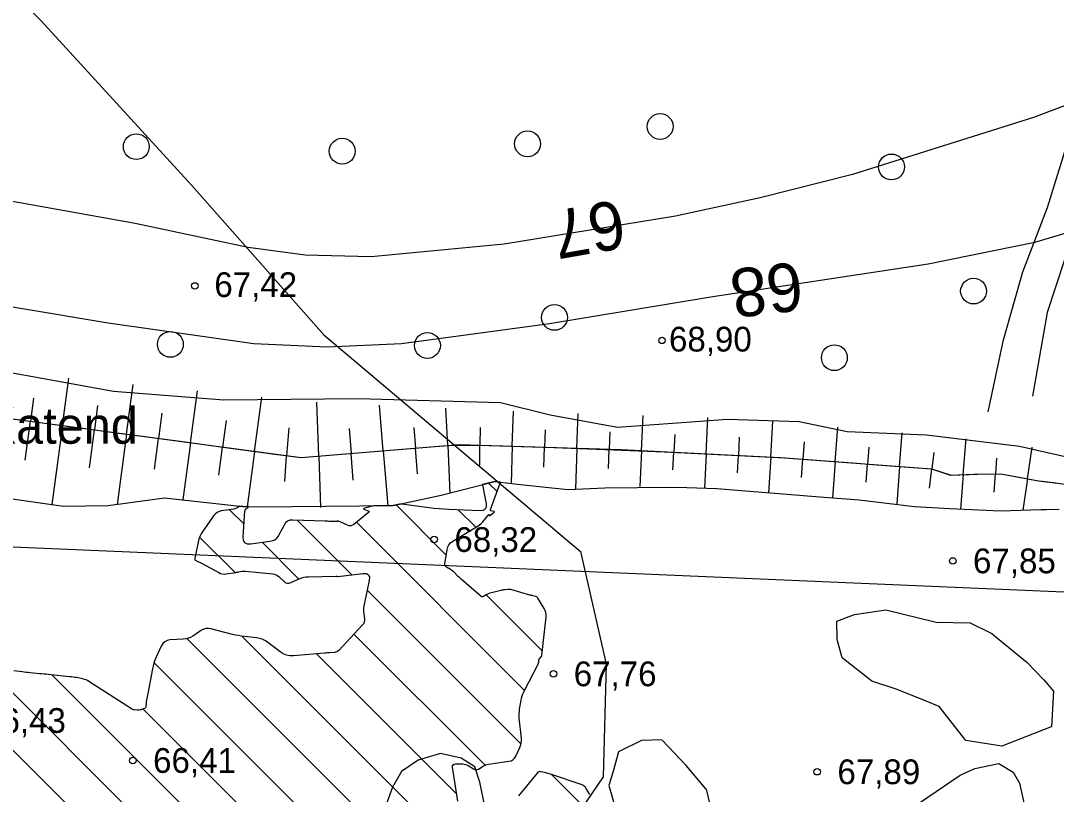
# Model space of a CAD drawing. Extents: x 532503 to 539665, y 6557663 to 6561526.
# Drawn here: x 535060.8 to 535163.3, y 6559795.9 to 6559872.5 of the extents above; entities that cross this region are included whole.
import ezdxf

# ---------------------------------------------------------------- set-up
doc = ezdxf.new("R2010")
doc.units = 0
for name, color, linetype in [('HALJASTUS', 7, 'Continuous'), ('HORISONTAAL-EH2000', 7, 'Continuous'), ('Kaevandatud ala', 7, 'Continuous'), ('KORGUS-EH2000', 7, 'Continuous'), ('Lamami horisontaal_EH2000', 7, 'Continuous'), ('Lõige', 7, 'Continuous'), ('RELJEEF', 7, 'Continuous'), ('TEE', 7, 'Continuous')]:
    doc.layers.add(name, color=color, linetype=linetype)

# ---------------------------------------------------------------- blocks, each defined once
blk = doc.blocks.new('METS')
at = {"layer": 'HALJASTUS'}
blk.add_circle((0, 0), 0.8, dxfattribs=at)

msp = doc.modelspace()

# ---------------------------------------------------------------- linework, layer by layer
at = {"layer": 'HORISONTAAL-EH2000'}
for points in [[(535305.89, 6559908.81), (535305.84, 6559908.81), (535298.2, 6559907.52), (535293.16, 6559905.66), (535283.2, 6559900.95), (535256.19, 6559889.33), (535239.19, 6559882.19), (535229.03, 6559879.32), (535223.83, 6559878.54), (535205.55, 6559877.82), (535200.02, 6559876.85), (535189.2, 6559873.55), (535161, 6559862.94), (535143.07, 6559857.27), (535133.96, 6559854.96), (535125.58, 6559853.17), (535108.62, 6559850.37), (535095.45, 6559849.12), (535088.9, 6559849.29), (535083.27, 6559850.06), (535072.08, 6559852.43), (535042.23, 6559857.77)], [(534983.62, 6559861.41), (534995.89, 6559858.28), (535002.31, 6559856.84), (535010.93, 6559854.84), (535015.15, 6559853.51), (535024.14, 6559850.04), (535030.28, 6559848.56), (535042.95, 6559847.02), (535069.4, 6559842.6), (535083.84, 6559840.56), (535091.09, 6559840.22), (535098.44, 6559840.55), (535113.09, 6559842.54), (535129.25, 6559845.19), (535150.59, 6559848.45), (535161.14, 6559850.59), (535196.02, 6559860.91), (535218.89, 6559866.28)]]:
    msp.add_lwpolyline(points, dxfattribs=at)
at = {"layer": 'Kaevandatud ala'}
for p, q in [((535107.07, 6559826.72), (535107.91, 6559825.88)), ((535081.42, 6559824.08), (535082.86, 6559822.64)), ((535097.92, 6559824.56), (535102.88, 6559819.59)), ((535104.06, 6559824.06), (535105.79, 6559822.34)), ((535088.12, 6559823.04), (535093.52, 6559817.64)), ((535093.98, 6559822.84), (535110.63, 6559806.18)), ((535078.46, 6559821.38), (535081.98, 6559817.86)), ((535084.68, 6559820.82), (535088.28, 6559817.22)), ((535095.05, 6559816.1), (535110.27, 6559800.89)), ((535106.82, 6559815.65), (535112.38, 6559810.09)), ((535093.73, 6559811.77), (535106.72, 6559798.78)), ((535077.22, 6559811.31), (535114.36, 6559774.17)), ((535082.63, 6559811.56), (535125.52, 6559768.67)), ((535090.04, 6559809.81), (535103.9, 6559795.95)), ((535051.56, 6559808.68), (535159.52, 6559700.73)), ((535057.33, 6559808.57), (535171.6, 6559694.3)), ((535073.95, 6559808.92), (535107.11, 6559775.77)), ((535063.84, 6559807.72), (535183.8, 6559687.76)), ((535072.88, 6559804.34), (535103.42, 6559773.8)), ((535113.33, 6559797.83), (535147.91, 6559763.25))]:
    msp.add_line(p, q, dxfattribs=at)
for points in [[(535106.47, 6559826.57), (535106.47, 6559826.56), (535106.81, 6559824.66), (535106.82, 6559824.35), (535106.73, 6559824.13), (535106.53, 6559824.01), (535106.22, 6559823.98), (535103.13, 6559824.1), (535102.64, 6559824.13), (535102.16, 6559824.16), (535101.67, 6559824.21), (535101.19, 6559824.27), (535098.44, 6559824.62), (535098.37, 6559824.63), (535098.29, 6559824.63), (535098.24, 6559824.63)], [(535104.01, 6559795.21), (535103.51, 6559798.58), (535103.51, 6559798.73), (535103.56, 6559798.83), (535103.65, 6559798.89), (535103.79, 6559798.91), (535104.49, 6559798.9), (535104.64, 6559798.89), (535104.78, 6559798.86), (535104.92, 6559798.81), (535105.05, 6559798.74), (535105.58, 6559798.41), (535105.7, 6559798.35), (535105.82, 6559798.33), (535105.94, 6559798.35), (535106.06, 6559798.4), (535106.53, 6559798.68), (535106.66, 6559798.75), (535106.78, 6559798.8), (535106.91, 6559798.84), (535107.05, 6559798.87), (535109.08, 6559799.17), (535109.3, 6559799.22), (535109.49, 6559799.33), (535109.64, 6559799.47), (535109.75, 6559799.67), (535110.15, 6559800.53), (535110.24, 6559800.74), (535110.29, 6559800.97), (535110.31, 6559801.19), (535110.31, 6559801.43), (535110.1, 6559803.46), (535110.09, 6559803.68), (535110.09, 6559803.9), (535110.11, 6559804.12), (535110.13, 6559804.34), (535110.28, 6559805.22), (535110.33, 6559805.43), (535110.39, 6559805.64), (535110.47, 6559805.85), (535110.56, 6559806.05), (535112, 6559808.86), (535112.01, 6559808.89), (535112.02, 6559808.92), (535112.03, 6559808.96), (535112.03, 6559808.99), (535112.03, 6559809.19), (535112.03, 6559809.2), (535112.03, 6559809.21), (535112.04, 6559809.22), (535112.04, 6559809.23), (535112.07, 6559809.26), (535112.08, 6559809.27), (535112.08, 6559809.28), (535112.09, 6559809.29), (535112.1, 6559809.3), (535112.26, 6559809.5), (535112.29, 6559809.53), (535112.31, 6559809.57), (535112.32, 6559809.61), (535112.33, 6559809.66), (535112.75, 6559813.47), (535112.75, 6559813.69), (535112.72, 6559813.9), (535112.66, 6559814.1), (535112.56, 6559814.3), (535111.95, 6559815.32), (535111.91, 6559815.38), (535111.86, 6559815.42), (535111.8, 6559815.46), (535111.73, 6559815.48), (535111.45, 6559815.55), (535111.38, 6559815.57), (535111.31, 6559815.59), (535111.24, 6559815.61), (535111.16, 6559815.63), (535109.36, 6559816.16), (535109.27, 6559816.18), (535109.18, 6559816.19), (535109.09, 6559816.19), (535109, 6559816.19), (535108.64, 6559816.15), (535108.55, 6559816.14), (535108.46, 6559816.12), (535108.37, 6559816.11), (535108.28, 6559816.08), (535107.08, 6559815.77), (535107.01, 6559815.74), (535106.95, 6559815.72), (535106.88, 6559815.69), (535106.82, 6559815.65), (535106.57, 6559815.49), (535106.51, 6559815.46), (535106.45, 6559815.45), (535106.39, 6559815.47), (535106.33, 6559815.5), (535104.35, 6559817.21), (535104.26, 6559817.29), (535104.18, 6559817.37), (535104.09, 6559817.45), (535104, 6559817.54), (535103.65, 6559817.89), (535103.57, 6559817.96), (535103.49, 6559818.03), (535103.4, 6559818.1), (535103.3, 6559818.16), (535102.91, 6559818.38), (535102.83, 6559818.45), (535102.78, 6559818.52), (535102.75, 6559818.61), (535102.75, 6559818.72), (535102.97, 6559820.13), (535103.03, 6559820.39), (535103.14, 6559820.61), (535103.31, 6559820.8), (535103.52, 6559820.96), (535106.03, 6559822.48), (535106.16, 6559822.57), (535106.29, 6559822.67), (535106.4, 6559822.77), (535106.5, 6559822.89), (535107.08, 6559823.6), (535107.09, 6559823.61), (535107.1, 6559823.62), (535107.11, 6559823.61), (535107.12, 6559823.59), (535107.15, 6559823.51), (535107.16, 6559823.49), (535107.17, 6559823.49), (535107.18, 6559823.49), (535107.2, 6559823.5), (535107.6, 6559823.81), (535107.63, 6559823.84), (535107.64, 6559823.87), (535107.62, 6559823.89), (535107.57, 6559823.91), (535107.33, 6559823.96), (535107.28, 6559823.98), (535107.25, 6559824.01), (535107.24, 6559824.05), (535107.25, 6559824.11), (535108.21, 6559826.7), (535108.22, 6559826.75), (535108.21, 6559826.79), (535108.2, 6559826.81)], [(535108.2, 6559826.81), (535107.67, 6559826.87), (535106.47, 6559826.57)], [(535082.4, 6559824.43), (535082.2, 6559824.28), (535082.11, 6559824.23), (535082.03, 6559824.19), (535081.94, 6559824.16), (535081.84, 6559824.14), (535080.61, 6559823.97), (535080.39, 6559823.91), (535080.19, 6559823.82), (535080.02, 6559823.68), (535079.87, 6559823.51), (535078.77, 6559821.95), (535078.61, 6559821.7), (535078.48, 6559821.44), (535078.38, 6559821.16), (535078.31, 6559820.88), (535077.98, 6559819.27), (535077.98, 6559819.2), (535077.99, 6559819.14), (535078.03, 6559819.09), (535078.09, 6559819.06), (535078.37, 6559818.93), (535078.44, 6559818.9), (535078.51, 6559818.86), (535078.57, 6559818.83), (535078.64, 6559818.79), (535080.36, 6559817.85), (535080.53, 6559817.78), (535080.71, 6559817.73), (535080.89, 6559817.71), (535081.08, 6559817.73), (535082.05, 6559817.87), (535082.13, 6559817.89), (535082.2, 6559817.9), (535082.28, 6559817.91), (535082.36, 6559817.93), (535082.68, 6559817.99), (535082.76, 6559818), (535082.84, 6559818.01), (535082.92, 6559818.01), (535083, 6559818), (535085.71, 6559817.72), (535085.88, 6559817.69), (535086.04, 6559817.63), (535086.19, 6559817.55), (535086.33, 6559817.44), (535086.85, 6559816.95), (535086.98, 6559816.85), (535087.13, 6559816.8), (535087.28, 6559816.8), (535087.44, 6559816.85), (535088.37, 6559817.26), (535088.58, 6559817.34), (535088.8, 6559817.4), (535089.02, 6559817.44), (535089.24, 6559817.45), (535091.96, 6559817.5), (535091.98, 6559817.5), (535091.99, 6559817.5), (535092.01, 6559817.49), (535092.03, 6559817.49), (535092.09, 6559817.47), (535092.11, 6559817.47), (535092.13, 6559817.47), (535092.14, 6559817.47), (535092.16, 6559817.47), (535094.61, 6559817.77), (535094.97, 6559817.77), (535095.19, 6559817.64), (535095.29, 6559817.41), (535095.26, 6559817.06), (535094.75, 6559814.71), (535094.72, 6559814.53), (535094.7, 6559814.36), (535094.69, 6559814.18), (535094.7, 6559814), (535094.78, 6559813.28), (535094.78, 6559813.11), (535094.74, 6559812.94), (535094.67, 6559812.79), (535094.56, 6559812.66), (535092.23, 6559810.15), (535092.14, 6559810.07), (535092.04, 6559810.01), (535091.93, 6559809.97), (535091.82, 6559809.95), (535091.33, 6559809.92), (535091.2, 6559809.91), (535091.08, 6559809.9), (535090.96, 6559809.89), (535090.84, 6559809.88), (535087.75, 6559809.61), (535087.39, 6559809.62), (535087.06, 6559809.68), (535086.74, 6559809.81), (535086.44, 6559810), (535085.18, 6559810.96), (535084.93, 6559811.12), (535084.67, 6559811.25), (535084.39, 6559811.34), (535084.1, 6559811.39), (535082.9, 6559811.52), (535082.6, 6559811.56), (535082.31, 6559811.61), (535082.01, 6559811.67), (535081.72, 6559811.74), (535079.57, 6559812.29), (535079.33, 6559812.33), (535079.09, 6559812.32), (535078.87, 6559812.25), (535078.65, 6559812.14), (535077.79, 6559811.57), (535077.57, 6559811.44), (535077.35, 6559811.35), (535077.1, 6559811.28), (535076.85, 6559811.25), (535075.53, 6559811.18), (535075.25, 6559811.13), (535075.01, 6559811.01), (535074.82, 6559810.83), (535074.67, 6559810.58), (535074.16, 6559809.47), (535074.04, 6559809.18), (535073.94, 6559808.9), (535073.86, 6559808.6), (535073.79, 6559808.31), (535073.23, 6559805.36), (535073.21, 6559805.27), (535073.2, 6559805.18), (535073.19, 6559805.09), (535073.18, 6559804.99), (535073.15, 6559804.57), (535073.14, 6559804.51), (535073.11, 6559804.46), (535073.07, 6559804.42), (535073.02, 6559804.39), (535072.71, 6559804.28), (535072.68, 6559804.27), (535072.65, 6559804.26), (535072.61, 6559804.25), (535072.58, 6559804.25), (535072.45, 6559804.23), (535072.41, 6559804.22), (535072.38, 6559804.22), (535072.35, 6559804.22), (535072.31, 6559804.22), (535071.98, 6559804.26), (535071.91, 6559804.27), (535071.85, 6559804.29), (535071.79, 6559804.32), (535071.73, 6559804.35), (535067.5, 6559807.08), (535067.36, 6559807.16), (535067.22, 6559807.23), (535067.07, 6559807.28), (535066.91, 6559807.32), (535066.27, 6559807.45), (535066.11, 6559807.48), (535065.95, 6559807.5), (535065.79, 6559807.52), (535065.63, 6559807.54), (535063.49, 6559807.76), (535063.27, 6559807.78), (535063.05, 6559807.8), (535062.83, 6559807.82), (535062.61, 6559807.84), (535061.7, 6559807.93), (535061.5, 6559807.95), (535061.3, 6559807.97), (535061.1, 6559808), (535060.89, 6559808.02), (535060.09, 6559808.13)], [(535083.28, 6559824.38), (535082.75, 6559824.39), (535082.4, 6559824.43)], [(535095.66, 6559824.47), (535094.78, 6559824.22), (535094.71, 6559824.2), (535094.69, 6559824.17), (535094.71, 6559824.14), (535094.78, 6559824.11), (535095.14, 6559823.98), (535095.21, 6559823.95), (535095.24, 6559823.91), (535095.23, 6559823.86), (535095.17, 6559823.8), (535093.72, 6559822.62), (535093.58, 6559822.54), (535093.43, 6559822.49), (535093.27, 6559822.5), (535093.11, 6559822.55), (535092.16, 6559822.99), (535092.15, 6559823), (535092.14, 6559823), (535092.13, 6559822.99), (535092.13, 6559822.98), (535092.11, 6559822.94), (535092.1, 6559822.93), (535092.09, 6559822.92), (535092.08, 6559822.92), (535092.07, 6559822.92), (535091.37, 6559822.93), (535091.25, 6559822.93), (535091.12, 6559822.94), (535091, 6559822.94), (535090.88, 6559822.94), (535087.67, 6559823.06), (535087.4, 6559823.04), (535087.16, 6559822.94), (535086.97, 6559822.79), (535086.82, 6559822.56), (535086.28, 6559821.52), (535086.12, 6559821.29), (535085.93, 6559821.11), (535085.7, 6559820.99), (535085.43, 6559820.92), (535083.54, 6559820.66), (535083.19, 6559820.67), (535082.94, 6559820.79), (535082.8, 6559821.02), (535082.78, 6559821.38), (535082.95, 6559823.96), (535082.96, 6559824.02), (535082.98, 6559824.07), (535083.01, 6559824.12), (535083.05, 6559824.16), (535083.25, 6559824.3), (535083.28, 6559824.34), (535083.29, 6559824.37), (535083.28, 6559824.38)], [(535098.24, 6559824.63), (535097.63, 6559824.49), (535095.66, 6559824.47)], [(535117.09, 6559795.85), (535117.02, 6559795.97), (535116.74, 6559796.47), (535116.66, 6559796.59), (535116.57, 6559796.68), (535116.46, 6559796.76), (535116.33, 6559796.82), (535113.18, 6559797.88), (535113.07, 6559797.91), (535112.95, 6559797.95), (535112.84, 6559797.98), (535112.72, 6559798.01), (535112.25, 6559798.13), (535112.14, 6559798.14), (535112.04, 6559798.13), (535111.95, 6559798.08), (535111.87, 6559798), (535110.03, 6559795.75)]]:
    msp.add_lwpolyline(points, dxfattribs=at)
at = {"layer": 'KORGUS-EH2000'}
for centre in [(535077.99, 6559846.25), (535124.23, 6559840.85), (535101.68, 6559821.13), (535153.01, 6559819.01), (535113.49, 6559807.83), (535071.86, 6559799.25), (535139.59, 6559798.13)]:
    msp.add_circle(centre, 0.32, dxfattribs=at)
at = {"layer": 'Lamami horisontaal_EH2000'}
msp.add_lwpolyline([(535055.19, 6559880.2), (535062.79, 6559872.51), (535077.69, 6559856.21), (535090.77, 6559841.4), (535116.17, 6559819.93), (535118.69, 6559808.77), (535118.39, 6559797.61), (535100.34, 6559771.01), (535084.6, 6559751.26), (535073.31, 6559736.88), (535073.11, 6559736.49), (535051.58, 6559715.86)], dxfattribs=at)
at = {"layer": 'Lõige'}
msp.add_lwpolyline([(533917.43, 6559650.43), (533949.04, 6559659.85), (534215.74, 6559786.31), (534470.46, 6559695.5), (534707.91, 6559763.06), (534929.16, 6559826.01), (535198.18, 6559814.49), (535305.66, 6559887.85), (535520.8, 6559960.87), (535543.92, 6559971)], dxfattribs=at)
at = {"layer": 'RELJEEF'}
for p, q in [((535064.88, 6559832.42), (535065.51, 6559837.1)), ((535071.22, 6559831.57), (535071.88, 6559836.47)), ((535077.57, 6559830.71), (535078.26, 6559835.85)), ((535083.91, 6559829.86), (535084.63, 6559835.22)), ((535062.02, 6559835.13), (535061.71, 6559832.85)), ((535068.37, 6559834.39), (535068.05, 6559831.99)), ((535090.26, 6559829.39), (535090.08, 6559834.72)), ((535096.64, 6559829.92), (535096.27, 6559834.44)), ((535074.73, 6559833.65), (535074.39, 6559831.14)), ((535103.02, 6559830.44), (535102.85, 6559834.14)), ((535109.41, 6559830.37), (535109.52, 6559833.84)), ((535115.81, 6559830.17), (535115.92, 6559833.61)), ((535122.2, 6559829.93), (535122.37, 6559833.41)), ((535128.6, 6559829.61), (535128.78, 6559833.21)), ((535061.19, 6559828.98), (535061.71, 6559832.85)), ((535064.88, 6559832.42), (535063.83, 6559824.61)), ((535081.09, 6559832.91), (535080.74, 6559830.29)), ((535087.28, 6559832.19), (535087.08, 6559829.43)), ((535099.66, 6559832.24), (535099.83, 6559830.18)), ((535106.23, 6559832.23), (535106.21, 6559830.47)), ((535134.99, 6559829.29), (535135.2, 6559832.85)), ((535141.37, 6559828.84), (535141.63, 6559832.27)), ((535067.55, 6559828.23), (535068.05, 6559831.99)), ((535071.22, 6559831.57), (535070.29, 6559824.61)), ((535073.99, 6559828.1), (535074.39, 6559831.14)), ((535093.25, 6559832.12), (535093.45, 6559829.65)), ((535112.66, 6559831.99), (535112.61, 6559830.27)), ((535119.07, 6559831.79), (535119.01, 6559830.07)), ((535125.49, 6559831.54), (535125.4, 6559829.77)), ((535131.88, 6559831.28), (535131.79, 6559829.45)), ((535147.75, 6559828.37), (535148.01, 6559831.7)), ((535077.57, 6559830.71), (535076.81, 6559825.06)), ((535080.36, 6559827.49), (535080.74, 6559830.29)), ((535100.04, 6559827.63), (535099.83, 6559830.18)), ((535103.02, 6559830.44), (535103.24, 6559825.73)), ((535106.19, 6559828.48), (535106.21, 6559830.47)), ((535109.41, 6559830.37), (535109.3, 6559826.69)), ((535112.55, 6559828.31), (535112.61, 6559830.27)), ((535115.81, 6559830.17), (535115.68, 6559826.12)), ((535138.3, 6559830.82), (535138.18, 6559829.08)), ((535144.69, 6559830.29), (535144.56, 6559828.6)), ((535154.04, 6559827.57), (535154.32, 6559831.09)), ((535160.4, 6559827.15), (535160.87, 6559830.28)), ((535083.91, 6559829.86), (535083.17, 6559824.37)), ((535086.89, 6559826.89), (535087.08, 6559829.43)), ((535090.26, 6559829.39), (535090.44, 6559824.31)), ((535093.67, 6559827.02), (535093.45, 6559829.65)), ((535096.64, 6559829.92), (535097.09, 6559824.48)), ((535118.94, 6559828.17), (535119.01, 6559830.07)), ((535122.2, 6559829.93), (535122.04, 6559826.39)), ((535125.31, 6559828.04), (535125.4, 6559829.77)), ((535128.6, 6559829.61), (535128.43, 6559826.23)), ((535131.71, 6559827.74), (535131.79, 6559829.45)), ((535134.99, 6559829.29), (535134.78, 6559825.74)), ((535138.05, 6559827.28), (535138.18, 6559829.08)), ((535151.15, 6559829.76), (535150.94, 6559828.12)), ((535157.35, 6559829.2), (535157.24, 6559827.64)), ((535141.37, 6559828.84), (535141.11, 6559825.26)), ((535144.43, 6559826.82), (535144.56, 6559828.6)), ((535147.75, 6559828.37), (535147.47, 6559824.62)), ((535150.7, 6559826.21), (535150.94, 6559828.12)), ((535154.04, 6559827.57), (535153.78, 6559824.14)), ((535157.12, 6559825.81), (535157.24, 6559827.64)), ((535160.4, 6559827.15), (535159.93, 6559824.04))]:
    msp.add_line(p, q, dxfattribs=at)
for points in [[(535235.61, 6559871.15), (535233.29, 6559871.98), (535228.96, 6559869.71), (535222.21, 6559864.31), (535202.72, 6559853.62), (535196.3, 6559850.51), (535185.26, 6559843.99), (535179.85, 6559839.35), (535172.84, 6559832.43), (535168.42, 6559829.1), (535166.19, 6559828.86), (535159.6, 6559830.35), (535150.4, 6559831.48), (535142.55, 6559831.8), (535137.8, 6559832.79), (535130.72, 6559833.01), (535119.84, 6559832.21), (535113.15, 6559833.46), (535108.23, 6559834.67), (535094.16, 6559835.07), (535080.86, 6559834.93), (535069.95, 6559835.78), (535052.44, 6559838.97)], [(535047.11, 6559834.81), (535088.5, 6559829.24), (535104.17, 6559830.54), (535120.2, 6559830.04), (535135.94, 6559829.25), (535150.91, 6559828.13), (535152.8, 6559827.51), (535155.08, 6559827.62), (535157.75, 6559827.64), (535161.5, 6559826.95), (535165.27, 6559826.48), (535169.29, 6559826.28), (535175, 6559831.53), (535184.65, 6559840.52), (535191.34, 6559844.88), (535200.32, 6559848.87), (535211.97, 6559854.51), (535218.28, 6559858.5), (535226.23, 6559864.44), (535232.63, 6559869.28), (535234.89, 6559870.61)], [(535059.91, 6559833.09), (535066.91, 6559832.15), (535070.43, 6559831.67), (535072.56, 6559831.39), (535073.09, 6559831.32), (535074.02, 6559831.19), (535077.02, 6559830.79), (535080.8, 6559830.28), (535084.24, 6559829.81), (535085.66, 6559829.62), (535088.5, 6559829.24), (535101.33, 6559830.3), (535103.1, 6559830.45), (535106.02, 6559830.48), (535113.56, 6559830.24), (535124.46, 6559829.82), (535136.43, 6559829.21), (535143.5, 6559828.68), (535145.5, 6559828.54), (535150.91, 6559828.13), (535152.86, 6559827.52), (535155.45, 6559827.62), (535157.75, 6559827.64), (535159.94, 6559827.24), (535161.31, 6559826.99), (535163.25, 6559826.73)], [(535052.72, 6559826.2), (535064.98, 6559824.45), (535069.41, 6559824.49), (535074.98, 6559825.26), (535082.75, 6559824.39), (535084.28, 6559824.36), (535097.63, 6559824.49), (535102.36, 6559825.54), (535107.67, 6559826.87), (535109.92, 6559826.62), (535113.33, 6559826.26), (535114.95, 6559826.09), (535118.56, 6559826.25), (535125.05, 6559826.31), (535126.69, 6559826.27), (535129.67, 6559826.2), (535140.27, 6559825.32), (535143.76, 6559825.07), (535149.23, 6559824.39), (535152.73, 6559824.19), (535157.72, 6559823.96), (535161.74, 6559824.09), (535162.29, 6559824.11), (535163.54, 6559824.15)], [(535162.74, 6559802.58), (535157.86, 6559800.68), (535154.31, 6559801.21), (535151.65, 6559804.58), (535150.39, 6559805.12), (535147.52, 6559806.29), (535145.01, 6559807.1), (535142.06, 6559809.41), (535141.57, 6559811.23), (535141.53, 6559813.03), (535143.28, 6559813.7), (535146.37, 6559814.18), (535151.37, 6559812.93), (535154.72, 6559812.89), (535156.89, 6559811.81), (535160.37, 6559808.96), (535162.03, 6559807.24), (535162.99, 6559806.11), (535162.79, 6559802.59)], [(535124.2, 6559801.3), (535122.2, 6559801.24), (535119.92, 6559800.11), (535119.42, 6559798.3), (535118.98, 6559796.76), (535119.83, 6559793.8), (535120.87, 6559789.08), (535119.8, 6559785.84), (535119.33, 6559783.26), (535120.04, 6559781.42), (535121.24, 6559778.67), (535123.39, 6559778.23), (535126.87, 6559778.34), (535129.13, 6559780.69), (535130.48, 6559783.89), (535130.78, 6559787.42), (535130.12, 6559791.61), (535129.12, 6559794.34), (535128.63, 6559796.39), (535128.58, 6559796.44), (535126.63, 6559798.76), (535124.25, 6559801.26)], [(535097.57, 6559796.6), (535095.59, 6559791.13), (535093.43, 6559783.87), (535093.51, 6559781.55), (535095.05, 6559779.39), (535096.55, 6559778.05), (535098.1, 6559778.35), (535100.12, 6559778.92), (535101.57, 6559780.72), (535103.44, 6559785.91), (535105.2, 6559789.68), (535106.11, 6559792.58), (535106.66, 6559794.67), (535106.7, 6559794.73), (535106.19, 6559797.09), (535105.71, 6559798.61), (535104.35, 6559799.46), (535102.29, 6559799.93), (535100.11, 6559799.29), (535098.45, 6559798.17), (535097.57, 6559796.6)], [(535149.72, 6559795.06), (535153.75, 6559797.8), (535155.2, 6559798.45), (535157.56, 6559798.95), (535158.99, 6559798.09), (535159.62, 6559796.99), (535160.08, 6559794.92)]]:
    msp.add_lwpolyline(points, dxfattribs=at)
at = {"layer": 'TEE'}
for points in [[(535156.5, 6559833.79), (535158.02, 6559840.91), (535159.95, 6559847.65), (535162.37, 6559854.02), (535167.01, 6559868.94), (535171.76, 6559883.25), (535176.74, 6559897.6), (535187.66, 6559925.84), (535193.11, 6559940.07), (535195.68, 6559949.91), (535197.96, 6559959.54), (535201.36, 6559968.73), (535205.14, 6559974.18), (535208.82, 6559978.67), (535215.85, 6559984.74), (535220.33, 6559991.48), (535223.5, 6559996.96), (535226.97, 6560003.49)], [(535229.77, 6560002.99), (535227.43, 6559997.91), (535223.16, 6559989.07), (535217.96, 6559980.75), (535211.48, 6559973.98), (535205.8, 6559968.14), (535203.2, 6559961.83), (535201.62, 6559956.33), (535200.33, 6559949.28), (535196.99, 6559938.07), (535186.54, 6559909.97), (535182.75, 6559899.27), (535177.79, 6559885.78), (535169.26, 6559863.82), (535165.75, 6559853.96), (535162.34, 6559843.63), (535160.9, 6559835.33)]]:
    msp.add_lwpolyline(points, dxfattribs=at)

# ---------------------------------------------------------------- block references
at = {"layer": 'HALJASTUS', "xscale": 1.6, "yscale": 1.6000000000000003}
for p in [(535124.05, 6559862.04), (535072.2, 6559860.04), (535092.58, 6559859.59), (535110.92, 6559860.32), (535146.94, 6559858.03), (535155.07, 6559845.74), (535113.59, 6559843.13), (535075.57, 6559840.46), (535101.01, 6559840.35), (535141.29, 6559839.14)]:
    msp.add_blockref('METS', p, dxfattribs=at)

# ---------------------------------------------------------------- texts
at = {"layer": 'HALJASTUS'}
msp.add_text('Katend', height=3.6, dxfattribs=at).set_placement((535057.09, 6559830.62))
at = {"layer": 'HORISONTAAL-EH2000'}
for s, rotation, p in [('67', 190.004, (535120.09, 6559854.83)), ('68', 186.6943, (535137.86, 6559848.66))]:
    msp.add_text(s, height=4.8, rotation=rotation, dxfattribs=at).set_placement(p)
at = {"layer": 'KORGUS-EH2000'}
for s, p in [('67,42', (535079.92, 6559845.15)), ('68,90', (535124.92, 6559839.75)), ('68,32 ', (535103.68, 6559819.9)), ('67,85 ', (535155.01, 6559817.79)), ('67,76 ', (535115.49, 6559806.6)), ('66,43 ', (535057.03, 6559801.98)), ('66,41 ', (535073.86, 6559798.02)), ('67,89 ', (535141.59, 6559796.9))]:
    msp.add_text(s, height=2.45, dxfattribs=at).set_placement(p)

doc.saveas('drawing.dxf')
